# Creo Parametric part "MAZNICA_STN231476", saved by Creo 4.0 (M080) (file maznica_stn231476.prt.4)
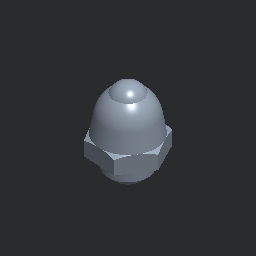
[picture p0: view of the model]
Units: millimeter Kilogram Sec (mmKs); MM, KILOGRAM, SECS
Materials in the file: OCEL_N

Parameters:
  MFG_WP_MATERIAL = "OCEL"
  NAZOV = "MAZNICA_STN231476"
  NORMA = "STN 23 1476"
  PTC_MATERIAL_NAME = "OCEL_N"

Other parameters: HMOTNOST, HUSTOTA, D8, D6, D10, D3

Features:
  1. datum plane "DTM1"
  2. cut
  3. chamfer
  4. datum plane "DTM2"
  5. datum plane "DTM3"

Other named items: BLIND

Layers: 1, 2, 3, 4, 5, 6, 7, 8, 9, 10, 11, 12, 13, 14, 15, 16, 17, 18, 19, 20, 21, 22, 23, 24, 25, 26, 27, 28, 29, 30, 31, 32

Family table entries: GENERIC, MAZNICA_M5, MAZNICA_STN231476, value(d_val), 2/$, value(i_val), MAZNICA_M6, MAZNICA_STN231476, 2/), 2/ , MAZNICA_M8X1, MAZNICA_STN231476, !/ , 2/2, 2/&, MAZNICA_M10X1, MAZNICA_STN231476, !/$, 2/4, 2/(, # Pro/TABLE, [] S 92;, [] W 10;, [A] W  3;, [B] W 14;, [C] W 10;, [D] W 10;, [E] W 10;, [F] W 10;, [G] W 10;, [H] W 10;, [I] W 10;, [J] W 10;, [K] W 10;

Surfaces: 11 plane, 6 cone, 4 cylinder, 4 torus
